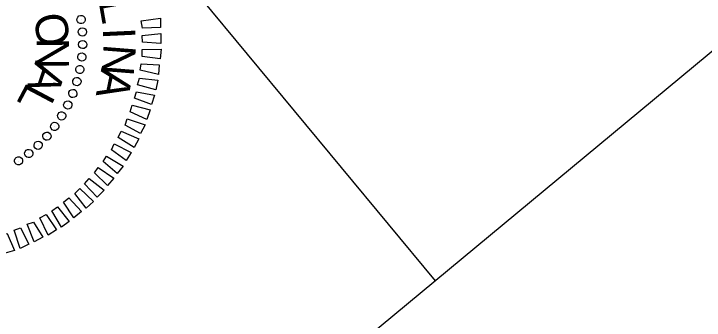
# Model space of a CAD drawing. Extents: x 2054826 to 2060231, y 685508 to 690809.
# Drawn here: x 2058800.7 to 2058981.3, y 687644.8 to 687724.9 of the extents above; entities that cross this region are included whole.
import ezdxf

# ---------------------------------------------------------------- set-up
doc = ezdxf.new("R2010")
doc.units = 0
doc.layers.add('Sheet Professional Seal CELL', color=7, linetype='Continuous')
doc.layers.add('Sheet Title CELL', color=7, linetype='Continuous')

msp = doc.modelspace()

# ---------------------------------------------------------------- linework, layer by layer
at = {"layer": 'Sheet Professional Seal CELL'}
for p, q in [((2058818.38, 687723.44), (2058818.38, 687723.44)), ((2058818.66, 687720.16), (2058818.66, 687720.16)), ((2058818.78, 687716.85), (2058818.78, 687716.85)), ((2058818.53, 687713.62), (2058818.53, 687713.62)), ((2058818.06, 687710.31), (2058818.06, 687710.31)), ((2058817.24, 687707.19), (2058817.24, 687707.19)), ((2058816.14, 687704.05), (2058816.14, 687704.05)), ((2058814.85, 687701.02), (2058814.85, 687701.02)), ((2058813.31, 687698.19), (2058813.31, 687698.19)), ((2058811.46, 687695.48), (2058811.46, 687695.48)), ((2058809.3, 687692.91), (2058809.3, 687692.91)), ((2058807.1, 687690.51), (2058807.1, 687690.51)), ((2058804.61, 687688.34), (2058804.61, 687688.34)), ((2058801.93, 687686.41), (2058801.93, 687686.41))]:
    msp.add_line(p, q, dxfattribs=at)
for points in [[(2058834, 687723.05), (2058839.03, 687723.8), (2058839.06, 687721.3), (2058834.36, 687721.2)], [(2058834.23, 687719.24), (2058839.18, 687719.74), (2058839.15, 687717.18), (2058834.33, 687717.48)], [(2058834.26, 687715.56), (2058839.23, 687715.69), (2058838.99, 687713.15), (2058834.31, 687713.75)], [(2058833.97, 687711.81), (2058838.74, 687711.58), (2058838.5, 687709.04), (2058833.76, 687710.18)], [(2058833.56, 687708.07), (2058838.36, 687707.56), (2058837.81, 687705.06), (2058833.08, 687706.3)], [(2058832.75, 687704.47), (2058837.52, 687703.65), (2058836.75, 687701.16), (2058832.23, 687702.86)], [(2058831.63, 687701), (2058836.36, 687699.76), (2058835.53, 687697.23), (2058831.14, 687699.24)], [(2058830.33, 687697.4), (2058835.03, 687695.84), (2058833.86, 687693.6), (2058829.81, 687695.79)], [(2058828.8, 687694.18), (2058833.36, 687692.21), (2058832.14, 687689.93), (2058828.01, 687692.55)], [(2058826.95, 687690.89), (2058831.37, 687688.62), (2058830.11, 687686.5), (2058826.22, 687689.31)], [(2058824.95, 687687.67), (2058829.34, 687685.08), (2058827.72, 687683.15), (2058824.07, 687686.26)], [(2058822.75, 687684.68), (2058826.86, 687681.95), (2058825.19, 687679.98), (2058821.83, 687683.33)], [(2058820.41, 687681.86), (2058824.33, 687678.78), (2058822.51, 687676.98), (2058819.22, 687680.48)], [(2058817.93, 687679.22), (2058821.5, 687675.85), (2058819.63, 687674.11), (2058816.64, 687677.95)], [(2058815.09, 687676.77), (2058818.37, 687673.16), (2058816.41, 687671.53), (2058813.7, 687675.62)], [(2058812.15, 687674.43), (2058815.15, 687670.58), (2058813.15, 687669.12), (2058810.67, 687673.4)], [(2058809.14, 687672.42), (2058811.86, 687668.44), (2058809.71, 687667.04), (2058807.52, 687671.56)], [(2058805.82, 687670.44), (2058808.32, 687666.48), (2058806.02, 687665.26), (2058804.22, 687669.9)], [(2058802.42, 687668.89), (2058804.64, 687664.69), (2058802.4, 687663.52), (2058800.83, 687668.35)], [(2058798.93, 687667.46), (2058800.86, 687663.02), (2058798.45, 687662.29), (2058797.19, 687667.09)]]:
    msp.add_lwpolyline(points, close=True, dxfattribs=at)
for centre, major_axis in [((2058818.29, 687723.43), (1.07, 0.16)), ((2058818.64, 687720.16), (1.08, 0.07)), ((2058818.71, 687716.88), (1.08, -0.03)), ((2058818.49, 687713.61), (1.07, -0.12)), ((2058817.98, 687710.36), (1.06, -0.21)), ((2058817.2, 687707.18), (1.04, -0.3)), ((2058816.14, 687704.07), (1.01, -0.39)), ((2058814.81, 687701.07), (0.968, -0.479)), ((2058813.23, 687698.19), (0.922, -0.562)), ((2058811.4, 687695.47), (0.87, -0.64)), ((2058809.35, 687692.91), (0.811, -0.713)), ((2058807.07, 687690.54), (0.746, -0.781)), ((2058804.6, 687688.38), (0.675, -0.843)), ((2058801.95, 687686.45), (0.599, -0.899))]:
    msp.add_ellipse(centre, major_axis=major_axis, ratio=0.999708, dxfattribs=at)
at = {"layer": 'Sheet Title CELL'}
for p, q in [((2058699.6, 687909.89), (2058910.89, 687655.09)), ((2058818.49, 687578.47), (2059003.24, 687731.67))]:
    msp.add_line(p, q, dxfattribs=at)

# ---------------------------------------------------------------- texts
at = {"layer": 'Sheet Professional Seal CELL'}
for s, rotation, p in [('L', 279.8881, (2058822.87, 687728.13)), ('O', 279.5007, (2058805.79, 687724.4)), ('I', 272.6873, (2058823.97, 687721.16)), ('N', 270.1438, (2058806.69, 687718.62)), ('N', 265.4861, (2058824.24, 687717.19)), ('A', 251.4275, (2058806.42, 687712.84)), ('A', 258.2844, (2058823.66, 687710.96)), ('L', 242.0681, (2058804.3, 687707.28))]:
    msp.add_text(s, height=8.46, rotation=rotation, dxfattribs=at).set_placement(p)

doc.saveas('drawing.dxf')
